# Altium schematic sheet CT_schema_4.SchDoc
size 245 x 200 mm
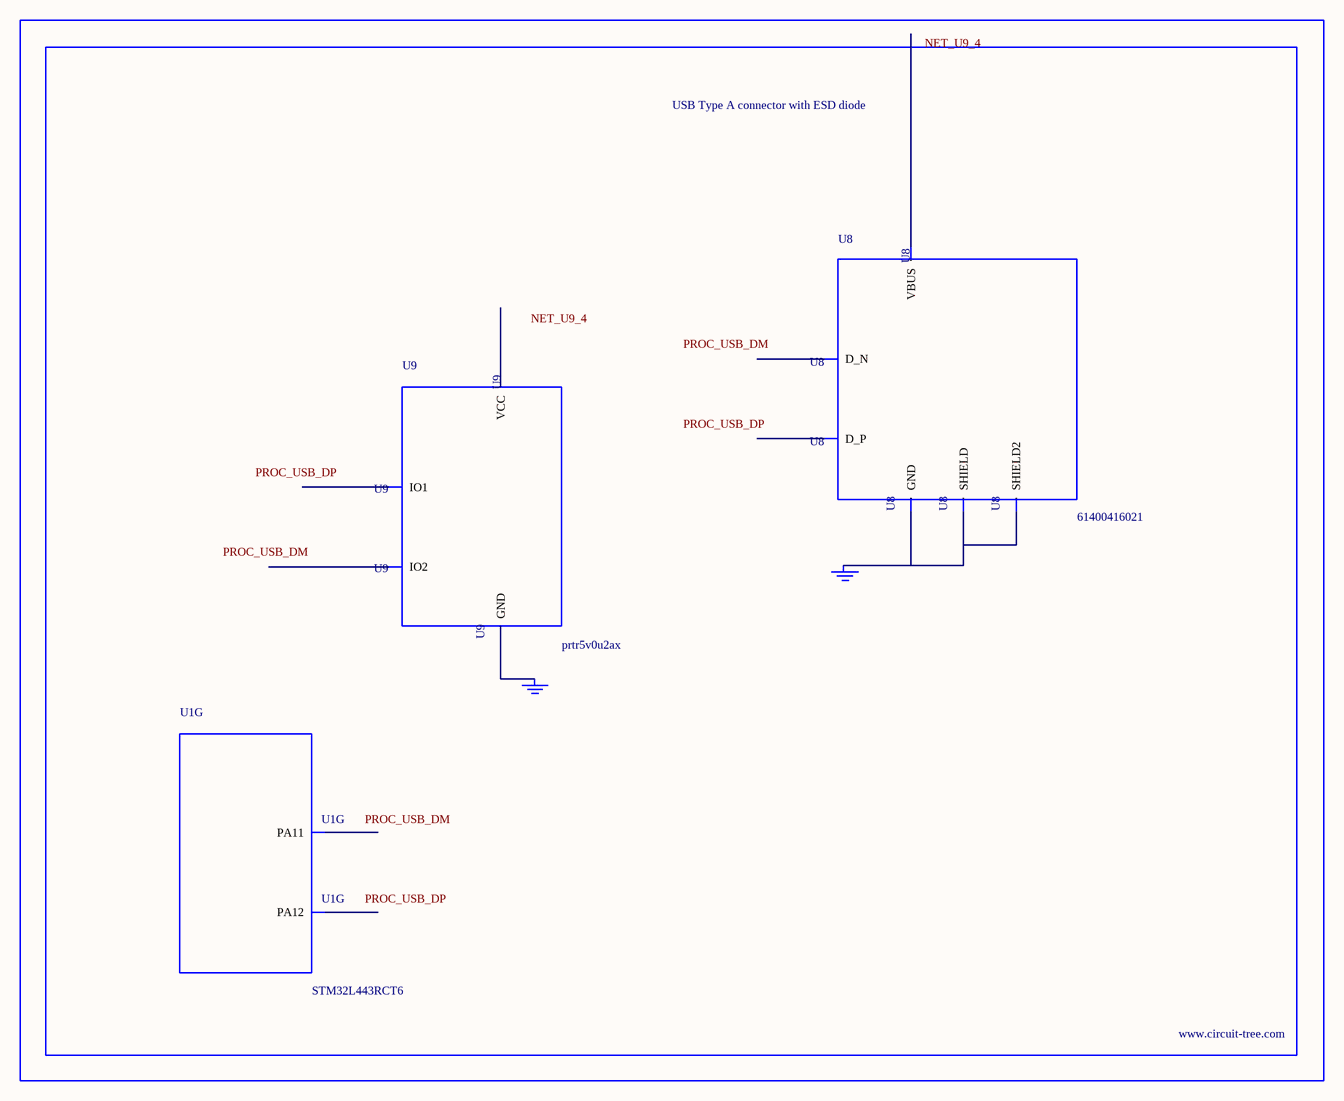
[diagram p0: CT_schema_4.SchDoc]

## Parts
BORDER3  (no value)
GND_INSTANCE_3_0  (no value)
GND_INSTANCE_3_1  (no value)
U1  STM32L443RCT6  [LQFP64]  (part G of 7)
U8  61400416021  [USB-A-H]
U9  prtr5v0u2ax  [SOT143B]

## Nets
NetGND_INSTANCE_3_0_0: GND_INSTANCE_3_0.0(GND) U8.4(GND) U8.5(SHIELD) U8.6(SHIELD2)
NetGND_INSTANCE_3_1_0: GND_INSTANCE_3_1.0(GND) U9.1(GND)

Not connected (* = marked no-connect by the designer): U1 44(PA11) 45(PA12); U8 1(VBUS) 2(D_N) 3(D_P); U9 2(IO1) 3(IO2) 4(VCC)

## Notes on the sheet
- Labels drawn without touching a wire or pin: NET_U9_4, PROC_USB_DM, PROC_USB_DP

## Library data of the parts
BORDER3 = BORDER_PAGE3
GND_INSTANCE_3_0 GND_INSTANCE_3_1 = GND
